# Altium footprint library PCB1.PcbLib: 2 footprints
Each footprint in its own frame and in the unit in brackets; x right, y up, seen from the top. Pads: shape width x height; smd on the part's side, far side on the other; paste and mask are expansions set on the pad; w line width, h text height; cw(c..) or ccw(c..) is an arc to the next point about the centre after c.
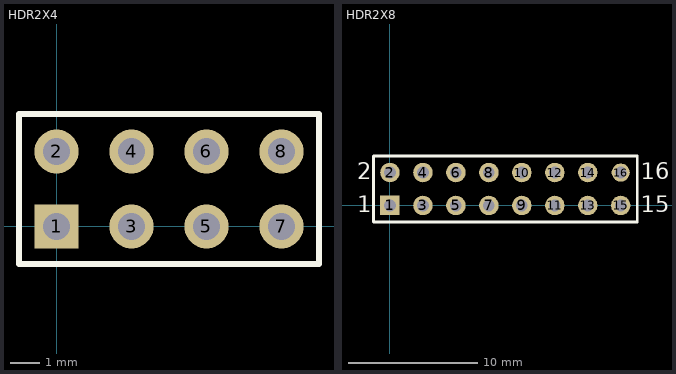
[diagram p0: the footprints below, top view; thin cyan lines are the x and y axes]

## HDR2X4 [mm] "Connector; Header; 4x2 Position"
pads (8):
  rect 1.5x1.5 hole 0.9: 1(0,0)
  round 1.5 hole 0.9: 2(0,2.54) 3(2.54,0) 4(2.54,2.54) 5(5.08,0) 6(5.08,2.54) 7(7.62,0) 8(7.62,2.54)
Top Overlay:
  lines w0.2: -1.27,-1.27 -1.27,3.81 8.89,3.81 8.89,-1.27 -1.27,-1.27

## HDR2X8 [mm] "Connector; Header; 8x2 Position"
pads (16):
  rect 1.5x1.5 hole 0.9: 1(0,0)
  round 1.5 hole 0.9: 2(0,2.54) 3(2.54,0) 4(2.54,2.54) 5(5.08,0) 6(5.08,2.54) 7(7.62,0) 8(7.62,2.54) 9(10.16,0) 10(10.16,2.54) 11(12.7,0) 12(12.7,2.54) 13(15.24,0) 14(15.24,2.54) 15(17.78,0)
  round 1.397 hole 0.9: 16(17.78,2.54)
Top Overlay:
  lines w0.2: -1.27,-1.27 -1.27,3.81 19.05,3.81 19.05,-1.27 -1.27,-1.27
  text "2" at -2.54,2.032 h1.27
  text "1" at -2.54,-0.508 h1.27
  text "15" at 19.304,-0.508 h1.27
  text "16" at 19.304,2.032 h1.27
